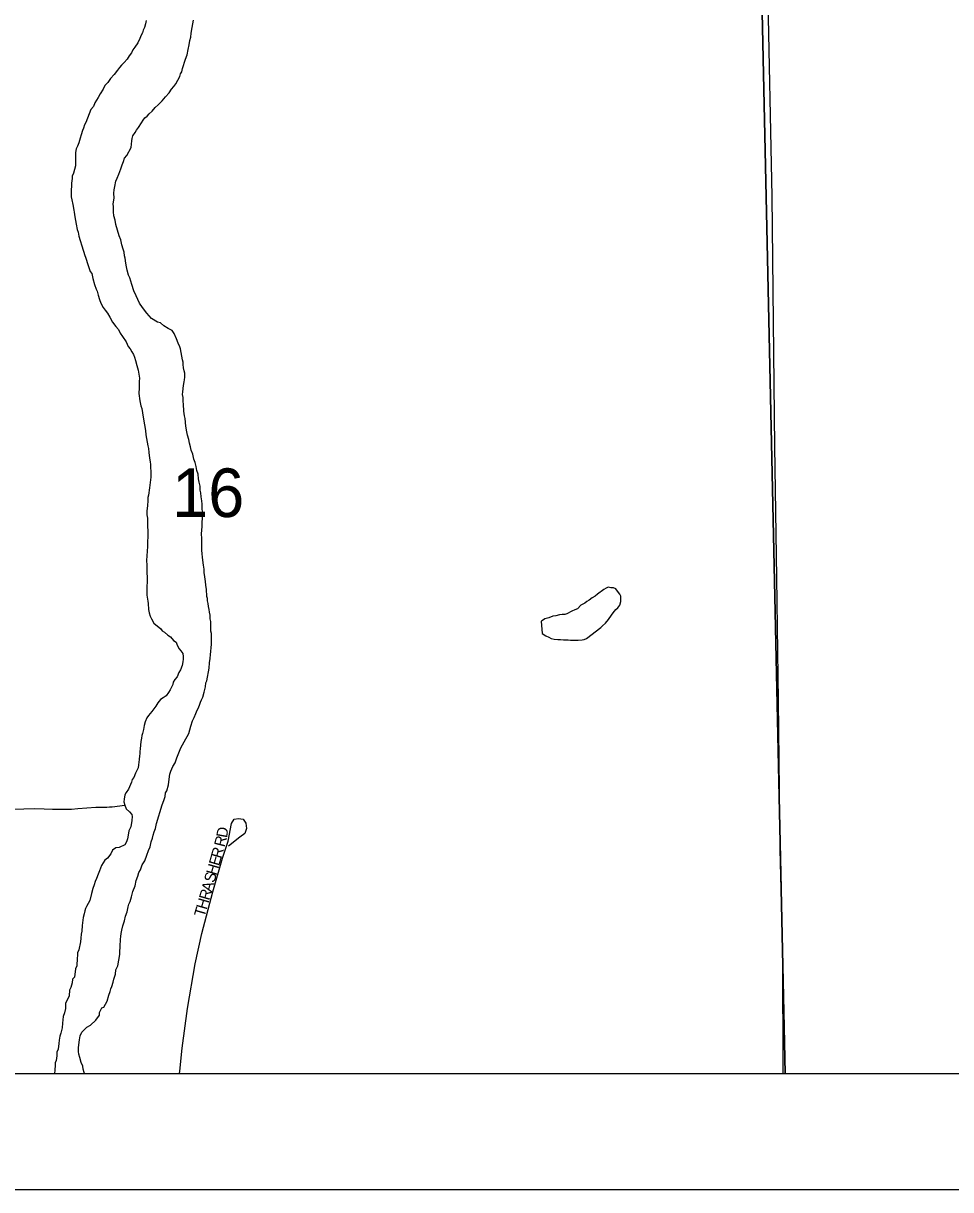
# Model space of a CAD drawing. Extents: x 10.6 to 44.6, y -2.6 to 23.4.
# Drawn here: x 16.631 to 17.431, y 15.426 to 16.432 of the extents above; entities that cross this region are included whole.
import ezdxf

# ---------------------------------------------------------------- set-up
doc = ezdxf.new("R2010")
doc.units = 0
for name, color, linetype in [('GM_X_County', 7, 'Continuous'), ('GM_X_Major_River', 7, 'Continuous'), ('GM_X_Minor_Lake', 7, 'Continuous'), ('GM_X_Minor_River', 7, 'Continuous'), ('GM_X_Section', 7, 'Continuous'), ('GM_X_Section_Text', 7, 'Continuous'), ('GM_X_Township', 7, 'Continuous'), ('GM_X_Township_Road', 7, 'Continuous'), ('GM_X_Township_Subdivision', 7, 'Continuous'), ('GM_X_Township_Subdivision_Text', 7, 'Continuous'), ('SH_Data', 7, 'Continuous')]:
    doc.layers.add(name, color=color, linetype=linetype)

msp = doc.modelspace()

# ---------------------------------------------------------------- linework, layer by layer
at = {"layer": 'GM_X_County'}
msp.add_lwpolyline([(20.0033, 15.5302), (20.0033, 22.3267), (13.2033, 22.3267), (13.2033, 15.5267), (19.8413, 15.5267)], dxfattribs=at)
at = {"layer": 'GM_X_Major_River'}
for points in [[(16.7369, 16.4344), (16.7362, 16.4313), (16.7355, 16.4283), (16.7344, 16.426), (16.7337, 16.4237), (16.7326, 16.4217), (16.7315, 16.4187), (16.7297, 16.4152), (16.7271, 16.4113), (16.7253, 16.409), (16.7242, 16.4063), (16.7223, 16.404), (16.7205, 16.4009), (16.7179, 16.3982), (16.7157, 16.3959), (16.7138, 16.3939), (16.712, 16.3916), (16.7094, 16.3877), (16.7061, 16.3842), (16.7039, 16.3808), (16.7012, 16.3784), (16.6998, 16.375), (16.6972, 16.3711), (16.6954, 16.368), (16.6939, 16.3657), (16.6925, 16.3634), (16.6914, 16.3603)], [(16.7183, 16.3156), (16.7201, 16.318), (16.7238, 16.3249), (16.7244, 16.3306), (16.7247, 16.3325), (16.7255, 16.3348), (16.7273, 16.3379), (16.7284, 16.3398), (16.7302, 16.3422), (16.7328, 16.346), (16.7343, 16.3483), (16.7358, 16.3503), (16.7376, 16.3518), (16.7395, 16.3538), (16.7421, 16.3561), (16.7447, 16.3592), (16.7473, 16.3616), (16.7506, 16.3651), (16.7536, 16.3686), (16.7566, 16.3721), (16.7588, 16.3752), (16.7606, 16.3775), (16.7625, 16.3798), (16.7643, 16.3829), (16.7658, 16.386), (16.7665, 16.3883), (16.7676, 16.3902), (16.7683, 16.3929), (16.7707, 16.4009), (16.7722, 16.4048), (16.7732, 16.4093), (16.7739, 16.4132), (16.7746, 16.417), (16.7753, 16.42), (16.7756, 16.4235), (16.7766, 16.4284), (16.7776, 16.4346)], [(16.6914, 16.3603), (16.6892, 16.3576), (16.6849, 16.3465), (16.6838, 16.3445), (16.6827, 16.3415), (16.682, 16.3395), (16.6809, 16.3357), (16.6798, 16.333), (16.6788, 16.3288), (16.6777, 16.3261), (16.6766, 16.3238), (16.6759, 16.3204), (16.676, 16.3177), (16.676, 16.3158), (16.6758, 16.309), (16.6741, 16.3028), (16.673, 16.3001), (16.673, 16.2982), (16.6727, 16.296), (16.6724, 16.294), (16.6724, 16.2914), (16.6721, 16.2883), (16.6722, 16.2853), (16.6722, 16.2822), (16.6727, 16.2796), (16.6735, 16.2758), (16.6744, 16.2709), (16.6748, 16.269), (16.6753, 16.2652), (16.6766, 16.2587), (16.6774, 16.2542), (16.6783, 16.2519), (16.6787, 16.2485), (16.6824, 16.2364), (16.6832, 16.2345), (16.6836, 16.2327), (16.6849, 16.2293), (16.6865, 16.224), (16.6886, 16.2179), (16.6901, 16.2161), (16.691, 16.2119), (16.6922, 16.2066), (16.6938, 16.2028), (16.6946, 16.2009), (16.6955, 16.1975), (16.6967, 16.1938), (16.6979, 16.1907), (16.6999, 16.187), (16.7015, 16.1847), (16.7034, 16.1821), (16.7054, 16.1787), (16.7078, 16.1742), (16.7106, 16.1705), (16.7129, 16.1679), (16.7145, 16.1649), (16.7165, 16.1619), (16.7196, 16.1574), (16.7212, 16.1532), (16.7232, 16.1514), (16.7244, 16.1487), (16.726, 16.1465), (16.7268, 16.1442), (16.7276, 16.1412), (16.7288, 16.137), (16.7301, 16.1329), (16.7305, 16.1295), (16.731, 16.126), (16.7307, 16.123), (16.7307, 16.1207), (16.7308, 16.1177), (16.7305, 16.1127), (16.7314, 16.1066), (16.7323, 16.1021), (16.7331, 16.0998), (16.7336, 16.096), (16.7345, 16.0907), (16.7353, 16.0858), (16.7362, 16.0809), (16.7367, 16.0771), (16.7384, 16.0676), (16.7388, 16.0653), (16.7393, 16.0619), (16.7398, 16.057), (16.7402, 16.054), (16.7407, 16.0517), (16.7407, 16.049), (16.7408, 16.0456), (16.7409, 16.0407), (16.7403, 16.0361), (16.7396, 16.0315), (16.739, 16.025), (16.7383, 16.0231), (16.7383, 16.0204), (16.7381, 16.0159), (16.7374, 16.0117), (16.7375, 16.0082), (16.7379, 16.0052), (16.738, 16.0014), (16.7381, 15.998), (16.7382, 15.9945), (16.7383, 15.9896)], [(16.7864, 15.9648), (16.7856, 15.969), (16.7855, 15.9716), (16.7851, 15.9747), (16.785, 15.9777), (16.7849, 15.9827), (16.7848, 15.9853), (16.7848, 15.9876), (16.7846, 15.9922), (16.785, 15.9948), (16.7853, 15.9983), (16.7852, 16.0021), (16.7855, 16.0048), (16.7858, 16.0105), (16.7853, 16.0127), (16.7853, 16.015), (16.7852, 16.0173), (16.7848, 16.0203), (16.7843, 16.0238), (16.7839, 16.0272), (16.7834, 16.0294), (16.7833, 16.0329), (16.7825, 16.0363), (16.7821, 16.0393), (16.7816, 16.0431), (16.7807, 16.0465), (16.7799, 16.0499), (16.7791, 16.0533), (16.7779, 16.0563), (16.777, 16.0605), (16.7758, 16.0639), (16.775, 16.0669), (16.7741, 16.0699), (16.7737, 16.073), (16.7724, 16.0768), (16.772, 16.0798), (16.7711, 16.0847), (16.7706, 16.0912), (16.7698, 16.0934), (16.7693, 16.0976), (16.7692, 16.1037), (16.7687, 16.106), (16.7687, 16.1094), (16.7682, 16.112), (16.7685, 16.1143), (16.7692, 16.1197), (16.7695, 16.1227), (16.7698, 16.1246), (16.7702, 16.1269), (16.7701, 16.1304), (16.7697, 16.1322), (16.7692, 16.1349), (16.7688, 16.1379), (16.7687, 16.1398), (16.7683, 16.1417), (16.7666, 16.1512), (16.7658, 16.1531), (16.7645, 16.1561), (16.7629, 16.1599), (16.7609, 16.1644), (16.7593, 16.167), (16.7559, 16.1688), (16.752, 16.171), (16.7493, 16.1736), (16.7466, 16.1743), (16.7416, 16.1773), (16.7373, 16.1821), (16.7338, 16.187), (16.731, 16.1907), (16.7282, 16.1971), (16.7262, 16.2013), (16.7246, 16.2066), (16.7229, 16.2126), (16.7217, 16.2149), (16.7205, 16.219), (16.72, 16.2221), (16.7192, 16.2251), (16.7187, 16.2293), (16.7183, 16.2315), (16.7178, 16.2346), (16.717, 16.2372), (16.7158, 16.241), (16.7149, 16.2452), (16.7137, 16.2486), (16.7108, 16.2584), (16.71, 16.2622), (16.7091, 16.266), (16.7087, 16.2694), (16.7086, 16.2736), (16.7085, 16.2762), (16.7092, 16.2812), (16.7091, 16.2854), (16.7094, 16.2884), (16.7097, 16.2911), (16.7107, 16.2957), (16.7118, 16.2984), (16.7133, 16.3018), (16.7151, 16.3064), (16.7161, 16.3099), (16.7172, 16.3129), (16.7183, 16.3156)], [(16.7383, 15.9896), (16.738, 15.985), (16.7381, 15.9812), (16.7378, 15.9767), (16.7375, 15.9732), (16.7372, 15.9686), (16.7373, 15.9652), (16.7374, 15.9626), (16.7375, 15.9588), (16.7376, 15.9538), (16.7377, 15.9496), (16.7374, 15.9473), (16.7375, 15.9428), (16.7375, 15.939), (16.738, 15.9356), (16.7384, 15.9337), (16.7385, 15.9318), (16.739, 15.9265), (16.7394, 15.9238), (16.7402, 15.9208), (16.7414, 15.9185), (16.7434, 15.9148), (16.7496, 15.91), (16.7508, 15.9081), (16.7527, 15.907), (16.7555, 15.9044), (16.7578, 15.9029), (16.7605, 15.8999), (16.7628, 15.8985), (16.7636, 15.8958), (16.7652, 15.8928), (16.7668, 15.8909), (16.7684, 15.8887), (16.7688, 15.886), (16.7689, 15.8838), (16.7685, 15.8815), (16.7678, 15.8784), (16.7664, 15.8746), (16.7649, 15.8722), (16.7635, 15.8684), (16.7617, 15.8661), (16.7602, 15.8638), (16.7599, 15.8619), (16.7577, 15.8572), (16.7562, 15.8549), (16.754, 15.8522), (16.7514, 15.8503), (16.7491, 15.8491), (16.7469, 15.846), (16.7451, 15.8433), (16.7417, 15.8386), (16.7388, 15.8351), (16.7373, 15.8332), (16.7359, 15.8297), (16.7352, 15.8267), (16.7345, 15.8232), (16.7338, 15.8198), (16.7331, 15.8179), (16.7328, 15.8156), (16.7324, 15.8129), (16.7321, 15.8095), (16.7318, 15.8064), (16.7315, 15.8041), (16.7315, 15.8022), (16.7312, 15.8003), (16.7309, 15.7973), (16.7302, 15.7927), (16.7299, 15.79), (16.7277, 15.7854), (16.7263, 15.7819), (16.7248, 15.78), (16.7241, 15.7777), (16.7234, 15.7758), (16.7216, 15.7716), (16.7197, 15.7689), (16.7186, 15.7669), (16.718, 15.7631), (16.7176, 15.7608), (16.7185, 15.7578), (16.7197, 15.7548), (16.7224, 15.7522), (16.7244, 15.7499), (16.7248, 15.748), (16.7245, 15.7446), (16.7235, 15.7393), (16.722, 15.7358), (16.7217, 15.7339), (16.7207, 15.7289), (16.72, 15.7263), (16.7185, 15.7236), (16.7136, 15.7215), (16.7106, 15.7211), (16.7079, 15.7191), (16.7065, 15.716), (16.7035, 15.7122), (16.7013, 15.7106), (16.6984, 15.706), (16.6966, 15.7014), (16.6955, 15.6983), (16.694, 15.6948), (16.693, 15.6921)], [(16.7072, 15.6015), (16.7083, 15.6054), (16.709, 15.608), (16.7104, 15.6123), (16.7107, 15.6161), (16.7125, 15.6195), (16.7142, 15.6291), (16.7144, 15.6382), (16.7147, 15.6405), (16.7146, 15.6424), (16.715, 15.6447), (16.7153, 15.6474), (16.716, 15.6501), (16.7167, 15.6539), (16.7181, 15.6581), (16.7191, 15.6623), (16.7206, 15.6661), (16.7212, 15.6703), (16.7219, 15.6726), (16.723, 15.6749), (16.7241, 15.6788), (16.7255, 15.6834), (16.7273, 15.6884), (16.7283, 15.693), (16.7298, 15.6968), (16.7305, 15.6999), (16.7319, 15.7022), (16.7333, 15.7064), (16.7356, 15.7099), (16.7373, 15.7148), (16.7388, 15.7187), (16.7402, 15.7221), (16.7413, 15.7264), (16.7423, 15.7294), (16.743, 15.7321), (16.7437, 15.7348), (16.7448, 15.7378), (16.7459, 15.7421), (16.7508, 15.7582), (16.7522, 15.762), (16.7533, 15.7654), (16.7536, 15.7685), (16.7547, 15.7704), (16.7561, 15.7754), (16.7571, 15.7826), (16.7574, 15.7846), (16.7581, 15.7872), (16.76, 15.7911), (16.7618, 15.7945), (16.7632, 15.7988), (16.765, 15.803), (16.7668, 15.8072), (16.7697, 15.8126), (16.7738, 15.8196), (16.7755, 15.8261), (16.7769, 15.8307), (16.7784, 15.8334), (16.7798, 15.8368), (16.7809, 15.8399), (16.782, 15.8418), (16.7831, 15.8449), (16.7838, 15.8468), (16.7845, 15.8487), (16.7856, 15.851), (16.787, 15.8552), (16.7881, 15.8598), (16.7884, 15.8633), (16.7891, 15.8652), (16.7911, 15.8759), (16.7914, 15.8805), (16.7921, 15.8843), (16.7924, 15.8877), (16.7927, 15.8904), (16.793, 15.8938), (16.7933, 15.8965), (16.7933, 15.8988), (16.7932, 15.901), (16.7931, 15.9033), (16.7931, 15.906), (16.7927, 15.9079), (16.7926, 15.9105), (16.7925, 15.9132), (16.7925, 15.9163), (16.792, 15.9185), (16.792, 15.9216), (16.7915, 15.9242), (16.7911, 15.9265), (16.7907, 15.9291), (16.7902, 15.9318), (16.7898, 15.9341), (16.7897, 15.936), (16.7893, 15.9379), (16.7893, 15.9398), (16.7888, 15.942), (16.7888, 15.9439), (16.7883, 15.9477), (16.7879, 15.9508), (16.7874, 15.9546), (16.7869, 15.9584), (16.7869, 15.9614), (16.7864, 15.9648)], [(16.693, 15.6921), (16.6919, 15.6891), (16.6908, 15.686), (16.6898, 15.6818), (16.6884, 15.6757), (16.6855, 15.6707), (16.6844, 15.6687), (16.684, 15.6668), (16.6833, 15.6642), (16.6826, 15.6611), (16.6823, 15.6588), (16.6817, 15.6542), (16.6814, 15.6493), (16.6807, 15.6466), (16.6804, 15.6432), (16.6801, 15.6401), (16.6787, 15.6332), (16.6776, 15.6305), (16.6777, 15.6283), (16.6774, 15.626), (16.6771, 15.6195), (16.676, 15.6168), (16.6751, 15.6096), (16.6732, 15.608), (16.6729, 15.6049), (16.6718, 15.6007), (16.6708, 15.5984), (16.6705, 15.5935), (16.6672, 15.5869), (16.6673, 15.5827), (16.6663, 15.5789), (16.6652, 15.5758), (16.6649, 15.5728), (16.6646, 15.5701), (16.6643, 15.5659), (16.6632, 15.5613), (16.6625, 15.5587), (16.6618, 15.5552), (16.6615, 15.5525), (16.6609, 15.5476), (16.6598, 15.5449), (16.6599, 15.5419), (16.6592, 15.5377), (16.6585, 15.5357), (16.6585, 15.5338), (16.6582, 15.5296), (16.6579, 15.5267)], [(16.6836, 15.5267), (16.6834, 15.5276), (16.6826, 15.5302), (16.6821, 15.5329), (16.6809, 15.5362), (16.6797, 15.5404), (16.6789, 15.5434), (16.6784, 15.5457), (16.6784, 15.5487), (16.6787, 15.5514), (16.6793, 15.5556), (16.68, 15.5591), (16.6815, 15.5621), (16.6833, 15.5641), (16.6856, 15.5664), (16.6889, 15.5684), (16.6934, 15.5727), (16.6967, 15.5769), (16.6967, 15.5792), (16.6985, 15.5831), (16.7004, 15.5839), (16.7033, 15.5889), (16.7047, 15.5942), (16.7058, 15.5973), (16.7065, 15.5996), (16.7072, 15.6015)]]:
    msp.add_lwpolyline(points, dxfattribs=at)
at = {"layer": 'GM_X_Minor_Lake'}
for points in [[(17.1291, 15.9111), (17.1304, 15.9125), (17.1331, 15.9149), (17.1356, 15.918), (17.1382, 15.9218), (17.1397, 15.9238), (17.1419, 15.9265), (17.1438, 15.928), (17.1453, 15.9303), (17.1463, 15.9334), (17.1463, 15.9353), (17.1462, 15.938), (17.1454, 15.9399), (17.1435, 15.9425), (17.1419, 15.9444), (17.14, 15.9454), (17.1377, 15.9454), (17.1354, 15.9457), (17.1335, 15.9449), (17.1316, 15.9437), (17.126, 15.9398), (17.1241, 15.9382), (17.1215, 15.9367), (17.1189, 15.9347), (17.117, 15.9335), (17.1152, 15.9319), (17.1118, 15.9304), (17.1088, 15.9272), (17.1065, 15.9264), (17.1039, 15.9252), (17.0998, 15.9228), (17.0979, 15.9224), (17.0956, 15.9224), (17.0933, 15.9219), (17.0903, 15.9211), (17.0876, 15.9207), (17.0842, 15.9195), (17.0808, 15.9186), (17.0786, 15.917), (17.0775, 15.9166)], [(17.0775, 15.9166), (17.0785, 15.906), (17.0816, 15.9038), (17.0842, 15.9027), (17.0862, 15.9016), (17.0889, 15.9009), (17.0919, 15.9006), (17.0942, 15.9006), (17.0969, 15.9003), (17.0988, 15.9004), (17.1007, 15.9004), (17.1029, 15.9001), (17.1056, 15.9001), (17.1094, 15.9002), (17.1128, 15.9003), (17.1147, 15.9007), (17.1166, 15.9015), (17.1291, 15.9111)]]:
    msp.add_lwpolyline(points, dxfattribs=at)
at = {"layer": 'GM_X_Minor_River'}
msp.add_lwpolyline([(16.6192, 15.7544), (16.6314, 15.7547), (16.6402, 15.7549), (16.6489, 15.7547), (16.6561, 15.7545), (16.6622, 15.7546), (16.6676, 15.7544), (16.6725, 15.7545), (16.6778, 15.755), (16.6934, 15.7561), (16.6991, 15.7562), (16.7029, 15.7563), (16.7052, 15.7564), (16.7071, 15.7564), (16.7075, 15.7564), (16.7185, 15.7578)], dxfattribs=at)
at = {"layer": 'GM_X_Section'}
for p, q in [((16.3159, 15.5267), (17.2881, 15.5267)), ((17.2881, 15.5267), (18.2299, 15.5267))]:
    msp.add_line(p, q, dxfattribs=at)
for points in [[(18.2299, 15.5267), (18.2074, 16.6265), (17.2647, 16.6007), (17.2881, 15.5267)], [(17.2881, 15.5267), (17.2647, 16.6007), (16.2932, 16.5791), (16.3159, 15.5267)]]:
    msp.add_lwpolyline(points, dxfattribs=at)
at = {"layer": 'GM_X_Township'}
msp.add_line((15.2903, 15.5267), (19.8413, 15.5267), dxfattribs=at)
at = {"layer": 'GM_X_Township_Road'}
msp.add_lwpolyline([(17.2723, 17.2948), (17.2673, 17.2939), (17.2641, 17.2912), (17.262, 17.2883), (17.261, 17.2854), (17.2602, 17.2806), (17.261, 17.2431), (17.2627, 17.1078), (17.2663, 16.8874), (17.2681, 16.7966), (17.2697, 16.6783), (17.2721, 16.5356), (17.2729, 16.465), (17.2766, 16.2826), (17.2787, 16.0672), (17.2806, 15.9542), (17.2819, 15.8478), (17.2835, 15.7197), (17.2856, 15.6289), (17.2861, 15.5267)], dxfattribs=at)
at = {"layer": 'GM_X_Township_Subdivision'}
msp.add_lwpolyline([(16.7656, 15.5267), (16.7658, 15.5287), (16.768, 15.5483), (16.7724, 15.5826), (16.7792, 15.6211), (16.7849, 15.6474), (16.7944, 15.6832), (16.8028, 15.7121), (16.8077, 15.727), (16.8104, 15.742), (16.8128, 15.7457), (16.8165, 15.7464), (16.8204, 15.7457), (16.8229, 15.7425), (16.8234, 15.7378), (16.8219, 15.7334), (16.8177, 15.7302), (16.8079, 15.7226)], dxfattribs=at)
at = {"layer": 'SH_Data'}
msp.add_line((13.1028, 15.4265), (20.1028, 15.4265), dxfattribs=at)

# ---------------------------------------------------------------- texts
at = {"layer": 'GM_X_Section_Text'}
msp.add_text('16', height=0.04186, rotation=0, dxfattribs=at).set_placement((16.7592, 16.0063))
at = {"layer": 'GM_X_Township_Subdivision_Text'}
for s, rotation, p in [('D', 79.9551, (16.8065, 15.7293)), ('R', 75.6012, (16.8044, 15.7213)), ('E', 73.9758, (16.7998, 15.705)), ('R', 73.9784, (16.8016, 15.7114)), ('H', 73.9957, (16.7975, 15.6969)), ('S', 73.975, (16.7956, 15.6905)), ('R', 73.9845, (16.7913, 15.6753)), ('A', 73.9706, (16.7933, 15.6825)), ('H', 73.982, (16.789, 15.6673)), ('T', 73.9758, (16.7871, 15.6609))]:
    msp.add_text(s, height=0.00947, rotation=rotation, dxfattribs=at).set_placement(p)

doc.saveas('drawing.dxf')
